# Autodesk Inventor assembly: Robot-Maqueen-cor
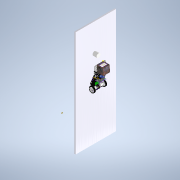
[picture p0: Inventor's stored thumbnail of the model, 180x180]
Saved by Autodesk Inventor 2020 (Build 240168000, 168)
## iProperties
Created: 2021-11
Part Number: Robot-Maqueen-cor
Document SubType Name: Assembly
Designer: bruno
Author: bruno
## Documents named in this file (9)
- C:\Users\bruno\OneDrive\Bureau\Robot-Inventor\Robot-equillibrage\Robot-Maqueen-cor.iam
- C:\Users\bruno\OneDrive\Bureau\Robot-Inventor\Robot-equillibrage\tapis.ipt
- C:\Users\bruno\OneDrive\Bureau\Robot-Inventor\Robot-equillibrage\Ensemble-base.iam
- C:\Users\bruno\OneDrive\Bureau\Robot-Inventor\Robot-equillibrage\Roulette.ipt
- C:\Users\bruno\OneDrive\Bureau\Robot-Inventor\Robot-equillibrage\roue.ipt
- C:\Users\bruno\OneDrive\Bureau\Robot-Inventor\Robot-equillibrage\Ensemble-pince.iam
- C:\Users\bruno\OneDrive\Bureau\Robot-Inventor\Robot-equillibrage\Ensemble-pince-2.iam
- C:\Users\bruno\OneDrive\Bureau\Robot-Inventor\Robot-equillibrage\support-colis.ipt
- C:\Users\bruno\OneDrive\Bureau\Robot-Inventor\Robot-equillibrage\colis.ipt
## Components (9 placed, 8 different names)
1. tapis:1 — Tangente:1, Tangente:2, Affleurement:1, Affleurement:2, Tangente:3, Placage:5
2. Ensemble-base:1 [sub-assembly] — Logement:2, Logement:3, Placage:1, Placage:2, Placage:3, Placage:4
3. Roulette:1 — Placage:1, Affleurement:2, Tangente:3
4. roue:1 — Logement:3, Tangente:2
5. roue:2 — Logement:2, Tangente:1, Affleurement:1
6. Ensemble-pince:1 [sub-assembly] — Placage:2, Affleurement:3, Rotation:1, Placage:6
7. Ensemble-pince-2:1 [sub-assembly] — Placage:3, Placage:4, Affleurement:3, Rotation:1, Placage:7
8. support-colis:1 — Placage:5
9. colis:1 — Placage:6, Placage:7
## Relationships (16: Mate 7, Tangent 3, Flush 3, Insert 2, RelateRotation 1)
- Logement:2 [Insert]: Ensemble-base:1 ↔ roue:2
- Logement:3 [Insert]: Ensemble-base:1 ↔ roue:1
- Tangente:1: tapis:1 ↔ roue:2
- Tangente:2: tapis:1 ↔ roue:1
- Affleurement:1 [Flush]: tapis:1 ↔ roue:2
- Placage:1 [Mate]: Ensemble-base:1 ↔ Roulette:1
- Affleurement:2 [Flush]: tapis:1 ↔ Roulette:1
- Tangente:3: tapis:1 ↔ Roulette:1
- Placage:2 [Mate]: Ensemble-base:1 ↔ Ensemble-pince:1
- Placage:3 [Mate]: Ensemble-base:1 ↔ Ensemble-pince-2:1
- Placage:4 [Mate]: Ensemble-base:1 ↔ Ensemble-pince-2:1
- Affleurement:3 [Flush]: Ensemble-pince:1 ↔ Ensemble-pince-2:1
- Rotation:1 [RelateRotation]: Ensemble-pince:1 ↔ Ensemble-pince-2:1
- Placage:5 [Mate]: tapis:1 ↔ support-colis:1
- Placage:6 [Mate]: Ensemble-pince:1 ↔ colis:1
- Placage:7 [Mate]: Ensemble-pince-2:1 ↔ colis:1
